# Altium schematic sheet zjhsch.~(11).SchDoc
size A4
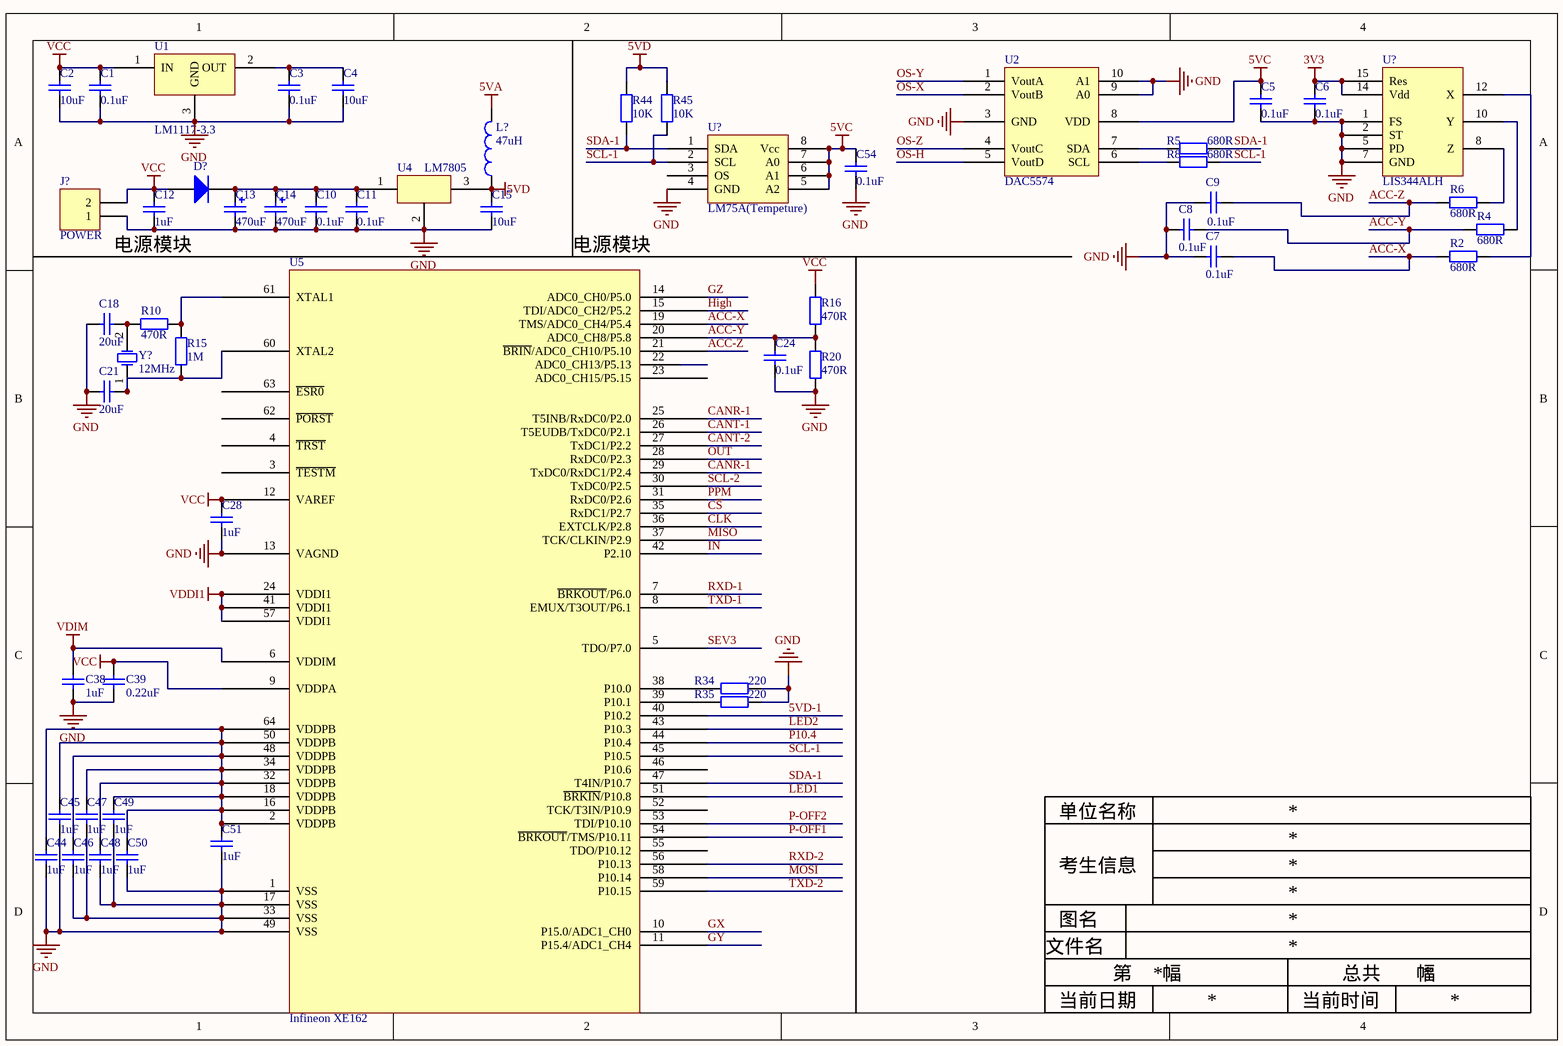
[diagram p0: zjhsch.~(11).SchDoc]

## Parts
(Parts that share a designator on the sheet are numbered #1, #2 ... from top to bottom, then left to right.)
C1  value 0.1uF  [RAD-0.3]  (hidden comment: Cap)
C2  value 10uF  [RAD-0.3]  (hidden comment: Cap)
C3  value 0.1uF  [RAD-0.3]  (hidden comment: Cap)
C4  value 10uF  [RAD-0.3]  (hidden comment: Cap)
C5  value 0.1uF  [RAD-0.3]  (hidden comment: Cap)
C6  value 0.1uF  [RAD-0.3]  (hidden comment: Cap)
C7  value 0.1uF  [RAD-0.3]  (hidden comment: Cap)
C8  value 0.1uF  [RAD-0.3]  (hidden comment: Cap)
C9  value 0.1uF  [RAD-0.3]  (hidden comment: Cap)
C10  value 0.1uF  [RAD-0.3]  (hidden comment: Cap)
C11  value 0.1uF  [RAD-0.3]  (hidden comment: Cap)
C12  value 1uF  [RAD-0.3]  (hidden comment: Cap)
C13  value 470uF  [POLAR0.8]  (hidden comment: Cap Pol2)
C14  value 470uF  [POLAR0.8]  (hidden comment: Cap Pol2)
C15  value 10uF  [RAD-0.3]  (hidden comment: Cap)
C18  value 20uF  [RAD-0.3]  (hidden comment: Cap)
C21  value 20uF  [RAD-0.3]  (hidden comment: Cap)
C24  value 0.1uF  [RAD-0.3]  (hidden comment: Cap)
C28  value 1uF  [RAD-0.3]  (hidden comment: Cap)
C38  value 1uF  [RAD-0.3]  (hidden comment: Cap)
C39  value 0.22uF  [RAD-0.3]  (hidden comment: Cap)
C44  value 1uF  [RAD-0.3]  (hidden comment: Cap)
C45  value 1uF  [RAD-0.3]  (hidden comment: Cap)
C46  value 1uF  [RAD-0.3]  (hidden comment: Cap)
C47  value 1uF  [RAD-0.3]  (hidden comment: Cap)
C48  value 1uF  [RAD-0.3]  (hidden comment: Cap)
C49  value 1uF  [RAD-0.3]  (hidden comment: Cap)
C50  value 1uF  [RAD-0.3]  (hidden comment: Cap)
C51  value 1uF  [RAD-0.3]  (hidden comment: Cap)
C54  value 0.1uF  [RAD-0.3]  (hidden comment: Cap)
D?  Diode  [SMC]  (value not drawn)
J?  POWER  [HDR1X2]
L?  47uH  [DIODE_SMC]
R2  680R  [R0603]
R4  680R  [R0603]
R5  680R  [R0603]
R6  680R  [R0603]
R8  680R  [R0603]
R10  470R  [1608[0603]]
R15  1M  [1608[0603]]
R16  470R  [R0603]
R20  470R  [R0603]
R34  220  [R0603]
R35  220  [R0603]
R44  10K  [1608[0603]]
R45  10K  [1608[0603]]
U1  LM1117-3.3  [LM1117-3.3]
U2  DAC5574
U4  LM7805  [TO-220AB]
U5  Infineon XE162  [Infineon XE162]
U?#1  LIS344ALH  [LIS344ALH(Acc)]
U?#2  LM75A(Tempeture)  [LM75A]
Y?  12MHz  [R38]

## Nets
3V3: C6.2 U?#1.14(Vdd) U?#1.15(Res)
5VA: L?.2
5VC: C5.2 C54.2 U2.8(VDD) U?#2.5(A2) U?#2.6(A1) U?#2.7(A0) U?#2.8(Vcc)
5VD: C15.2 L?.1 R44.2 R45.2 U4.3
GND: C1.1 C2.1 C3.1 C4.1 C5.1 C6.1 C7.2 C8.2 C9.2 C10.1 C11.1 C12.1 C13.2 C14.2 C15.1 C18.2 C21.2 C24.1 C28.1 C38.2 C39.2 C44.1 C45.1 C46.1 C47.1 C48.1 C49.1 C50.1 C51.1 C54.1 J?.1 R20.1 R34.1 R35.1 U1.3(GND) U2.3(GND) U2.9(A0) U2.10(A1) U4.2 U5.1(VSS) U5.13(VAGND) U5.17(VSS) U5.33(VSS) U5.49(VSS) U?#1.1(FS) U?#1.2(ST) U?#1.5(PD) U?#1.7(GND) U?#2.4(GND)
VCC: C1.2 C2.2 C12.2 C28.2 C39.1 D?.1(A) J?.2 R16.2 U1.1(IN) U5.9(VDDPA) U5.12(VAREF)
VDDI1: U5.24(VDDI1) U5.41(VDDI1) U5.57(VDDI1)
VDIM: C38.1 U5.6(VDDIM)
5VD-1: U5.40(P10.2)
ACC-X: C7.1 R2.2 U5.19(TMS/ADC0_CH4/P5.4)
ACC-Y: C8.1 C24.2 R4.2 R16.1 R20.2 U5.20(ADC0_CH8/P5.8)
ACC-Z: C9.1 R6.2 U5.21(~{BRIN}/ADC0_CH10/P5.10)
CANR-1: U5.25(T5INB/RxDC0/P2.0) U5.29(TxDC0/RxDC1/P2.4)
CANT-1: U5.26(T5EUDB/TxDC0/P2.1)
CANT-2: U5.27(TxDC1/P2.2)
CLK: U5.36(EXTCLK/P2.8)
C~{S}: U5.35(RxDC1/P2.7)
GX: U5.10(P15.0/ADC1_CH0)
GY: U5.11(P15.4/ADC1_CH4)
GZ: U5.14(ADC0_CH0/P5.0)
High: U5.15(TDI/ADC0_CH2/P5.2)
IN: U5.42(P2.10)
LED1: U5.51(~{BRKIN}/P10.8)
LED2: U5.43(P10.3)
MISO: U5.37(TCK/CLKIN/P2.9)
MOSI: U5.58(P10.14)
OS-H: U2.5(VoutD)
OS-X: U2.2(VoutB)
OS-Y: U2.1(VoutA)
OS-Z: U2.4(VoutC)
OUT: U5.28(RxDC0/P2.3)
P10.4: U5.44(P10.4)
P-OFF1: U5.54(~{BRKOUT}/TMS/P10.11)
P-OFF2: U5.53(TDI/P10.10)
PPM: U5.31(RxDC0/P2.6)
RXD-1: U5.7(~{BRKOUT}/P6.0)
RXD-2: U5.56(P10.13)
SCL-1: R8.2 R45.1 U5.45(P10.5) U?#2.2(SCL)
SCL-2: U5.30(TxDC0/P2.5)
SDA-1: R5.2 R44.1 U5.47(T4IN/P10.7) U?#2.1(SDA)
SEV3: U5.5(TDO/P7.0)
TXD-1: U5.8(EMUX/T3OUT/P6.1)
TXD-2: U5.59(P10.15)
NetC3_2: C3.2 C4.2 U1.2(OUT)
NetC10_2: C10.2 C11.2 C13.1 C14.1 D?.2(K) U4.1
NetC18_1: C18.1 R10.2 Y?.2(OSC2)
NetC21_1: C21.1 R15.1 U5.60(XTAL2) Y?.1(OSC1)
NetC44_2: C44.2 C45.2 C46.2 C47.2 C48.2 C49.2 C50.2 C51.2 U5.2(VDDPB) U5.16(VDDPB) U5.18(VDDPB) U5.32(VDDPB) U5.34(VDDPB) U5.48(VDDPB) U5.50(VDDPB) U5.64(VDDPB)
NetR2_1: R2.1 U?#1.12(X)
NetR4_1: R4.1 U?#1.10(Y)
NetR5_1: R5.1 U2.7(SDA)
NetR6_1: R6.1 U?#1.8(Z)
NetR8_1: R8.1 U2.6(SCL)
NetR10_1: R10.1 R15.2 U5.61(XTAL1)
NetR34_2: R34.2 U5.38(P10.0)
NetR35_2: R35.2 U5.39(P10.1)

Not connected (* = marked no-connect by the designer): U5 3(~{TESTM}) 4(~{TRST}) 22(ADC0_CH13/P5.13) 23(ADC0_CH15/P5.15) 46(P10.6) 52(TCK/T3IN/P10.9) 55(TDO/P10.12) 62(~{PORST}) 63(~{ESR0}); U?#2 3(OS)

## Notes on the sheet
- 单位名称
- 考生信息
- 图名
- 文件名
- 第      幅
- 总共       幅
- 当前日期
- 当前时间
- Labels drawn without touching a wire or pin: 电源模块

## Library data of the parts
C1-C12 C15 C18 C21 C24 C28 C38 C39 C44-C51 C54 = Cap: Capacitor
C13 C14 = Cap Pol2: Polarized Capacitor (Axial)
D? = Diode: Default Diode
J? = Header 2: Header, 2-Pin
L? = Inductor47uH
R2 R4-R6 R8 R16 R20 R34 R35 = R0603
R10 R15 R44 R45 = R0805
U4 = 7805
U?#1 = ACC(LIS344ALH)
Y? = XTAL: Crystal Oscillator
